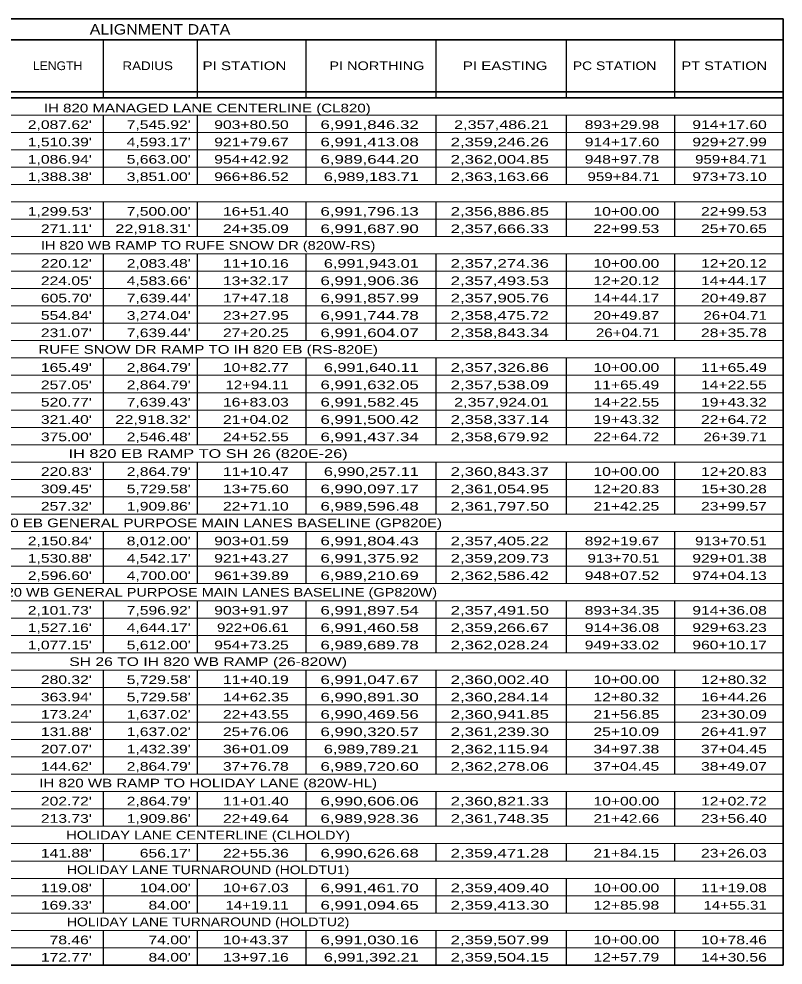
# Model space of a CAD drawing. Extents: x 1953053 to 1967065, y 7363860 to 7371201.
# Drawn here: x 1962633 to 1963690, y 7368856 to 7370165 of the extents above; entities that cross this region are included whole.
import ezdxf
from ezdxf.enums import TextEntityAlignment as Align

# ---------------------------------------------------------------- set-up
doc = ezdxf.new("R2010")
doc.units = 0
doc.header["$LTSCALE"] = 4.8
doc.layers.add('10', color=7, linetype='Continuous')
doc.layers.add('12', color=7, linetype='Continuous', lineweight=25)

msp = doc.modelspace()

# ---------------------------------------------------------------- linework, layer by layer
at = {"layer": '12', "lineweight": 35}
for p, q in [((1963689.794, 7370164.879), (1961966.462, 7370164.879)), ((1963689.794, 7368855.748), (1963689.794, 7370164.879)), ((1961966.462, 7370136.079), (1963689.794, 7370136.079)), ((1961966.462, 7370064.079), (1963689.794, 7370064.079)), ((1961966.462, 7370055.746), (1963689.794, 7370055.746)), ((1961966.462, 7368855.748), (1963689.794, 7368855.748))]:
    msp.add_line(p, q, dxfattribs=at)
at = {"layer": '12'}
for p, q in [((1962749.794, 7370136.079), (1962749.794, 7370055.746)), ((1962879.794, 7370136.079), (1962879.794, 7370055.746)), ((1963029.794, 7370136.079), (1963029.794, 7370055.746)), ((1963209.794, 7370136.079), (1963209.794, 7370055.746)), ((1963389.794, 7370136.079), (1963389.794, 7370055.746)), ((1963539.794, 7370136.079), (1963539.794, 7370055.746)), ((1962749.794, 7370031.746), (1962749.794, 7369935.746)), ((1962879.794, 7370031.746), (1962879.794, 7369935.746)), ((1963029.794, 7370031.746), (1963029.794, 7369935.746)), ((1963209.794, 7370031.746), (1963209.794, 7369935.746)), ((1963389.794, 7370031.746), (1963389.794, 7369935.746)), ((1963539.794, 7370031.746), (1963539.794, 7369935.746)), ((1962749.794, 7369911.746), (1962749.794, 7369863.746)), ((1962879.794, 7369911.746), (1962879.794, 7369863.746)), ((1963029.794, 7369911.746), (1963029.794, 7369863.746)), ((1963209.794, 7369911.746), (1963209.794, 7369863.746)), ((1963389.794, 7369911.746), (1963389.794, 7369863.746)), ((1963539.794, 7369911.746), (1963539.794, 7369863.746)), ((1962749.794, 7369839.746), (1962749.794, 7369719.746)), ((1962879.794, 7369839.746), (1962879.794, 7369719.746)), ((1963029.794, 7369839.746), (1963029.794, 7369719.746)), ((1963209.794, 7369839.746), (1963209.794, 7369719.746)), ((1963389.794, 7369839.746), (1963389.794, 7369719.746)), ((1963539.794, 7369839.746), (1963539.794, 7369719.746)), ((1962749.794, 7369695.746), (1962749.794, 7369575.746)), ((1962879.794, 7369695.746), (1962879.794, 7369575.746)), ((1963029.794, 7369695.746), (1963029.794, 7369575.746)), ((1963209.794, 7369695.746), (1963209.794, 7369575.746)), ((1963389.794, 7369695.746), (1963389.794, 7369575.746)), ((1963539.794, 7369695.746), (1963539.794, 7369575.746)), ((1962749.794, 7369551.746), (1962749.794, 7369479.746)), ((1962879.794, 7369551.746), (1962879.794, 7369479.746)), ((1963029.794, 7369551.746), (1963029.794, 7369479.746)), ((1963209.794, 7369551.746), (1963209.794, 7369479.746)), ((1963389.794, 7369551.746), (1963389.794, 7369479.746)), ((1963539.794, 7369551.746), (1963539.794, 7369479.746)), ((1962749.794, 7369455.746), (1962749.794, 7369383.746)), ((1962879.794, 7369455.746), (1962879.794, 7369383.746)), ((1963029.794, 7369455.746), (1963029.794, 7369383.746)), ((1963209.794, 7369455.746), (1963209.794, 7369383.746)), ((1963389.794, 7369455.746), (1963389.794, 7369383.746)), ((1963539.794, 7369455.746), (1963539.794, 7369383.746)), ((1962749.794, 7369359.746), (1962749.794, 7369287.746)), ((1962879.794, 7369359.746), (1962879.794, 7369287.746)), ((1963029.794, 7369359.746), (1963029.794, 7369287.746)), ((1963209.794, 7369359.746), (1963209.794, 7369287.746)), ((1963389.794, 7369359.746), (1963389.794, 7369287.746)), ((1963539.794, 7369359.746), (1963539.794, 7369287.746)), ((1962749.794, 7369263.746), (1962749.794, 7369119.746)), ((1962879.794, 7369263.746), (1962879.794, 7369119.746)), ((1963029.794, 7369263.746), (1963029.794, 7369119.746)), ((1963209.794, 7369263.746), (1963209.794, 7369119.746)), ((1963389.794, 7369263.746), (1963389.794, 7369119.746)), ((1963539.794, 7369263.746), (1963539.794, 7369119.746)), ((1962749.794, 7369095.746), (1962749.794, 7369047.747)), ((1962879.794, 7369095.746), (1962879.794, 7369047.747)), ((1963029.794, 7369095.746), (1963029.794, 7369047.747)), ((1963209.794, 7369095.746), (1963209.794, 7369047.747)), ((1963389.794, 7369095.746), (1963389.794, 7369047.747)), ((1963539.794, 7369095.746), (1963539.794, 7369047.747)), ((1962749.794, 7369023.747), (1962749.794, 7368999.747)), ((1962879.794, 7369023.747), (1962879.794, 7368999.747)), ((1963029.794, 7369023.747), (1963029.794, 7368999.747)), ((1963209.794, 7369023.747), (1963209.794, 7368999.747)), ((1963389.794, 7369023.747), (1963389.794, 7368999.747)), ((1963539.794, 7369023.747), (1963539.794, 7368999.747)), ((1962749.794, 7368975.747), (1962749.794, 7368927.747)), ((1962879.794, 7368975.747), (1962879.794, 7368927.747)), ((1963029.794, 7368975.747), (1963029.794, 7368927.747)), ((1963209.794, 7368975.747), (1963209.794, 7368927.747)), ((1963389.794, 7368975.747), (1963389.794, 7368927.747)), ((1963539.794, 7368975.747), (1963539.794, 7368927.747)), ((1962749.794, 7368903.747), (1962749.794, 7368855.747)), ((1962879.794, 7368903.747), (1962879.794, 7368855.747)), ((1963029.794, 7368903.747), (1963029.794, 7368855.747)), ((1963209.794, 7368903.747), (1963209.794, 7368855.747)), ((1963389.794, 7368903.747), (1963389.794, 7368855.747)), ((1963539.794, 7368903.747), (1963539.794, 7368855.747))]:
    msp.add_line(p, q, dxfattribs=at)
at = {"layer": '12', "lineweight": 13}
for p, q in [((1961966.462, 7370031.746), (1963689.794, 7370031.746)), ((1961966.462, 7370007.746), (1963689.794, 7370007.746)), ((1961966.462, 7369983.746), (1963689.794, 7369983.746)), ((1961966.462, 7369959.746), (1963689.794, 7369959.746)), ((1961966.462, 7369935.746), (1963689.794, 7369935.746)), ((1961966.462, 7369911.746), (1963689.794, 7369911.746)), ((1961966.462, 7369887.746), (1963689.794, 7369887.746)), ((1961966.462, 7369863.746), (1963689.794, 7369863.746)), ((1961966.462, 7369839.746), (1963689.794, 7369839.746)), ((1961966.462, 7369815.746), (1963689.794, 7369815.746)), ((1961966.462, 7369791.746), (1963689.794, 7369791.746)), ((1961966.462, 7369767.746), (1963689.794, 7369767.746)), ((1961966.462, 7369743.746), (1963689.794, 7369743.746)), ((1961966.462, 7369719.746), (1963689.794, 7369719.746)), ((1961966.462, 7369695.746), (1963689.794, 7369695.746)), ((1961966.462, 7369671.746), (1963689.794, 7369671.746)), ((1961966.462, 7369647.746), (1963689.794, 7369647.746)), ((1961966.462, 7369623.746), (1963689.794, 7369623.746)), ((1961966.462, 7369599.746), (1963689.794, 7369599.746)), ((1961966.462, 7369575.746), (1963689.794, 7369575.746)), ((1961966.462, 7369527.746), (1963689.794, 7369527.746)), ((1961966.462, 7369503.746), (1963689.794, 7369503.746)), ((1961966.462, 7369479.746), (1963689.794, 7369479.746)), ((1961966.462, 7369455.746), (1963689.794, 7369455.746)), ((1961966.462, 7369431.746), (1963689.794, 7369431.746)), ((1961966.462, 7369407.746), (1963689.794, 7369407.746)), ((1961966.462, 7369383.746), (1963689.794, 7369383.746)), ((1961966.462, 7369359.746), (1963689.794, 7369359.746)), ((1961966.462, 7369335.746), (1963689.794, 7369335.746)), ((1961966.462, 7369311.746), (1963689.794, 7369311.746)), ((1961966.462, 7369287.746), (1963689.794, 7369287.746)), ((1961966.462, 7369263.746), (1963689.794, 7369263.746)), ((1961966.462, 7369239.746), (1963689.794, 7369239.746)), ((1961966.462, 7369215.746), (1963689.794, 7369215.746)), ((1961966.462, 7369191.746), (1963689.794, 7369191.746)), ((1961966.462, 7369167.746), (1963689.794, 7369167.746)), ((1961966.462, 7369143.746), (1963689.794, 7369143.746)), ((1961966.462, 7369119.746), (1963689.794, 7369119.746)), ((1961966.462, 7369095.746), (1963689.794, 7369095.746)), ((1961966.462, 7369071.746), (1963689.794, 7369071.746)), ((1961966.462, 7369047.747), (1963689.794, 7369047.747)), ((1961966.462, 7369023.747), (1963689.794, 7369023.747)), ((1961966.462, 7368999.747), (1963689.794, 7368999.747)), ((1961966.462, 7368975.747), (1963689.794, 7368975.747)), ((1961966.462, 7368951.747), (1963689.794, 7368951.747)), ((1961966.462, 7368927.748), (1963689.794, 7368927.748)), ((1961966.462, 7368903.748), (1963689.794, 7368903.748)), ((1961966.462, 7368879.748), (1963689.794, 7368879.748))]:
    msp.add_line(p, q, dxfattribs=at)
msp.add_lwpolyline([(1961966.462, 7369551.746), (1962489.198, 7369551.746), (1963689.794, 7369551.746)], dxfattribs=at)

# ---------------------------------------------------------------- texts
at = {"layer": '10'}
for s, width, p in [('IH 820 MANAGED LANE CENTERLINE (CL820)', 1.3, (1962893.586, 7370035.509)), ('IH 820 WB RAMP TO RUFE SNOW DR (820W-RS)', 1.25, (1962894.794, 7369845.54)), ('RUFE SNOW DR RAMP TO IH 820 EB (RS-820E)', 1.3, (1962894.794, 7369701.54)), ('IH 820 EB RAMP TO SH 26 (820E-26)', 1.4, (1962894.794, 7369557.54)), ('IH 820 EB GENERAL PURPOSE MAIN LANES BASELINE (GP820E)', 1.3, (1962894.795, 7369461.54)), ('IH 820 WB GENERAL PURPOSE MAIN LANES BASELINE (GP820W)', 1.25, (1962894.795, 7369365.54)), ('SH 26 TO IH 820 WB RAMP (26-820W)', 1.35, (1962894.794, 7369269.54)), ('IH 820 WB RAMP TO HOLIDAY LANE (820W-HL)', 1.3, (1962894.794, 7369101.54)), ('HOLIDAY LANE CENTERLINE (CLHOLDY)', 1.25, (1962894.794, 7369029.541)), ('HOLIDAY LANE TURNAROUND (HOLDTU1)', 1.2, (1962894.794, 7368981.541)), ('HOLIDAY LANE TURNAROUND (HOLDTU2)', 1.2, (1962894.794, 7368909.542))]:
    msp.add_text(s, height=12, dxfattribs=dict(at, width=width)).set_placement(p, align=Align.CENTER)
for s, width, p in [("2,087.62'", 1.35, (1962733.918, 7370012.573)), ("7,545.92'", 1.35, (1962870.687, 7370012.573)), ('903+80.50', 1.35, (1963006.231, 7370012.573)), ('6,991,846.32', 1.45, (1963185.996, 7370012.573)), ('2,357,486.21', 1.4, (1963365.996, 7370012.573)), ('893+29.98', 1.35, (1963518.574, 7370012.573)), ('914+17.60', 1.35, (1963667.306, 7370012.573)), ("1,510.39'", 1.35, (1962733.918, 7369988.573)), ("4,593.17'", 1.35, (1962870.687, 7369988.573)), ('921+79.67', 1.35, (1963006.231, 7369988.573)), ('6,991,413.08', 1.45, (1963185.996, 7369988.573)), ('2,359,246.26', 1.45, (1963365.996, 7369988.573)), ('914+17.60', 1.35, (1963518.574, 7369988.573)), ('929+27.99', 1.35, (1963667.306, 7369988.573)), ("1,086.94'", 1.35, (1962733.918, 7369964.573)), ("5,663.00'", 1.35, (1962870.687, 7369964.573)), ('954+42.92', 1.35, (1963006.231, 7369964.573)), ('6,989,644.20', 1.45, (1963185.996, 7369964.573)), ('2,362,004.85', 1.45, (1963365.996, 7369964.573)), ('948+97.78', 1.35, (1963518.574, 7369964.573)), ('959+84.71', 1.3, (1963667.306, 7369964.573)), ("1,388.38'", 1.35, (1962733.918, 7369940.573)), ("3,851.00'", 1.35, (1962870.687, 7369940.573)), ('966+86.52', 1.35, (1963006.231, 7369940.573)), ('6,989,183.71', 1.4, (1963185.996, 7369940.573)), ('2,363,163.66', 1.45, (1963365.996, 7369940.573)), ('959+84.71', 1.3, (1963518.574, 7369940.573)), ('973+73.10', 1.35, (1963667.306, 7369940.573)), ("1,299.53'", 1.35, (1962733.918, 7369892.573)), ("7,500.00'", 1.35, (1962870.687, 7369892.573)), ('16+51.40', 1.35, (1963006.231, 7369892.573)), ('6,991,796.13', 1.45, (1963185.996, 7369892.573)), ('2,356,886.85', 1.45, (1963365.996, 7369892.573)), ('10+00.00', 1.35, (1963518.574, 7369892.573)), ('22+99.53', 1.35, (1963667.306, 7369892.573)), ("271.11'", 1.35, (1962733.918, 7369868.573)), ("22,918.31'", 1.4, (1962870.687, 7369868.573)), ('24+35.09', 1.35, (1963006.231, 7369868.573)), ('6,991,687.90', 1.45, (1963185.996, 7369868.573)), ('2,357,666.33', 1.45, (1963365.996, 7369868.573)), ('22+99.53', 1.35, (1963518.574, 7369868.573)), ('25+70.65', 1.35, (1963667.306, 7369868.573)), ("220.12'", 1.35, (1962733.918, 7369820.573)), ("2,083.48'", 1.35, (1962870.687, 7369820.573)), ('11+10.16', 1.35, (1963006.231, 7369820.573)), ('6,991,943.01', 1.4, (1963185.996, 7369820.573)), ('2,357,274.36', 1.45, (1963365.996, 7369820.573)), ('10+00.00', 1.35, (1963518.574, 7369820.573)), ('12+20.12', 1.35, (1963667.306, 7369820.573)), ("224.05'", 1.35, (1962733.918, 7369796.573)), ("4,583.66'", 1.35, (1962870.687, 7369796.573)), ('13+32.17', 1.35, (1963006.231, 7369796.573)), ('6,991,906.36', 1.45, (1963185.996, 7369796.573)), ('2,357,493.53', 1.45, (1963365.996, 7369796.573)), ('12+20.12', 1.35, (1963518.574, 7369796.573)), ('14+44.17', 1.35, (1963667.306, 7369796.573)), ("605.70'", 1.35, (1962733.918, 7369772.573)), ("7,639.44'", 1.35, (1962870.687, 7369772.573)), ('17+47.18', 1.35, (1963006.231, 7369772.573)), ('6,991,857.99', 1.45, (1963185.996, 7369772.573)), ('2,357,905.76', 1.45, (1963365.996, 7369772.573)), ('14+44.17', 1.35, (1963518.574, 7369772.573)), ('20+49.87', 1.35, (1963667.306, 7369772.573)), ("554.84'", 1.35, (1962733.918, 7369748.573)), ("3,274.04'", 1.35, (1962870.687, 7369748.573)), ('23+27.95', 1.35, (1963006.231, 7369748.573)), ('6,991,744.78', 1.45, (1963185.996, 7369748.573)), ('2,358,475.72', 1.45, (1963365.996, 7369748.573)), ('20+49.87', 1.35, (1963518.574, 7369748.573)), ('26+04.71', 1.3, (1963667.306, 7369748.573)), ("231.07'", 1.35, (1962733.918, 7369724.573)), ("7,639.44'", 1.35, (1962870.687, 7369724.573)), ('27+20.25', 1.35, (1963006.231, 7369724.573)), ('6,991,604.07', 1.45, (1963185.996, 7369724.573)), ('2,358,843.34', 1.45, (1963365.996, 7369724.573)), ('26+04.71', 1.3, (1963518.574, 7369724.573)), ('28+35.78', 1.35, (1963667.306, 7369724.573)), ("165.49'", 1.35, (1962733.918, 7369676.573)), ("2,864.79'", 1.35, (1962870.687, 7369676.573)), ('10+82.77', 1.35, (1963006.231, 7369676.573)), ('6,991,640.11', 1.4, (1963185.996, 7369676.573)), ('2,357,326.86', 1.45, (1963365.996, 7369676.573)), ('10+00.00', 1.35, (1963518.574, 7369676.573)), ('11+65.49', 1.35, (1963667.306, 7369676.573)), ("257.05'", 1.35, (1962733.918, 7369652.573)), ("2,864.79'", 1.35, (1962870.687, 7369652.573)), ('12+94.11', 1.3, (1963006.231, 7369652.573)), ('6,991,632.05', 1.45, (1963185.996, 7369652.573)), ('2,357,538.09', 1.45, (1963365.996, 7369652.573)), ('11+65.49', 1.35, (1963518.574, 7369652.573)), ('14+22.55', 1.35, (1963667.306, 7369652.573)), ("520.77'", 1.35, (1962733.918, 7369628.573)), ("7,639.43'", 1.35, (1962870.687, 7369628.573)), ('16+83.03', 1.35, (1963006.231, 7369628.573)), ('6,991,582.45', 1.45, (1963185.996, 7369628.573)), ('2,357,924.01', 1.4, (1963365.996, 7369628.573)), ('14+22.55', 1.35, (1963518.574, 7369628.573)), ('19+43.32', 1.35, (1963667.306, 7369628.573)), ("321.40'", 1.35, (1962733.918, 7369604.573)), ("22,918.32'", 1.4, (1962870.687, 7369604.573)), ('21+04.02', 1.35, (1963006.231, 7369604.573)), ('6,991,500.42', 1.45, (1963185.996, 7369604.573)), ('2,358,337.14', 1.45, (1963365.996, 7369604.573)), ('19+43.32', 1.35, (1963518.574, 7369604.573)), ('22+64.72', 1.35, (1963667.306, 7369604.573)), ("375.00'", 1.35, (1962733.918, 7369580.573)), ("2,546.48'", 1.35, (1962870.687, 7369580.573)), ('24+52.55', 1.35, (1963006.231, 7369580.573)), ('6,991,437.34', 1.45, (1963185.996, 7369580.573)), ('2,358,679.92', 1.45, (1963365.996, 7369580.573)), ('22+64.72', 1.35, (1963518.574, 7369580.573)), ('26+39.71', 1.3, (1963667.306, 7369580.573)), ("220.83'", 1.35, (1962733.918, 7369532.573)), ("2,864.79'", 1.35, (1962870.687, 7369532.573)), ('11+10.47', 1.35, (1963006.231, 7369532.573)), ('6,990,257.11', 1.4, (1963185.996, 7369532.573)), ('2,360,843.37', 1.45, (1963365.996, 7369532.573)), ('10+00.00', 1.35, (1963518.574, 7369532.573)), ('12+20.83', 1.35, (1963667.306, 7369532.573)), ("309.45'", 1.35, (1962733.918, 7369508.573)), ("5,729.58'", 1.35, (1962870.687, 7369508.573)), ('13+75.60', 1.35, (1963006.231, 7369508.573)), ('6,990,097.17', 1.45, (1963185.996, 7369508.573)), ('2,361,054.95', 1.45, (1963365.996, 7369508.573)), ('12+20.83', 1.35, (1963518.574, 7369508.573)), ('15+30.28', 1.35, (1963667.306, 7369508.573)), ("257.32'", 1.35, (1962733.918, 7369484.573)), ("1,909.86'", 1.35, (1962870.687, 7369484.573)), ('22+71.10', 1.35, (1963006.231, 7369484.573)), ('6,989,596.48', 1.45, (1963185.996, 7369484.573)), ('2,361,797.50', 1.45, (1963365.996, 7369484.573)), ('21+42.25', 1.35, (1963518.574, 7369484.573)), ('23+99.57', 1.35, (1963667.306, 7369484.573)), ("2,150.84'", 1.35, (1962733.918, 7369436.573)), ("8,012.00'", 1.35, (1962870.687, 7369436.573)), ('903+01.59', 1.35, (1963006.231, 7369436.573)), ('6,991,804.43', 1.45, (1963185.996, 7369436.573)), ('2,357,405.22', 1.45, (1963365.996, 7369436.573)), ('892+19.67', 1.35, (1963518.574, 7369436.573)), ('913+70.51', 1.3, (1963667.306, 7369436.573)), ("1,530.88'", 1.35, (1962733.918, 7369412.573)), ("4,542.17'", 1.35, (1962870.687, 7369412.573)), ('921+43.27', 1.35, (1963006.231, 7369412.573)), ('6,991,375.92', 1.45, (1963185.996, 7369412.573)), ('2,359,209.73', 1.45, (1963365.996, 7369412.573)), ('913+70.51', 1.3, (1963518.574, 7369412.573)), ('929+01.38', 1.35, (1963667.306, 7369412.573)), ("2,596.60'", 1.35, (1962733.918, 7369388.573)), ("4,700.00'", 1.35, (1962870.687, 7369388.573)), ('961+39.89', 1.35, (1963006.231, 7369388.573)), ('6,989,210.69', 1.45, (1963185.996, 7369388.573)), ('2,362,586.42', 1.45, (1963365.996, 7369388.573)), ('948+07.52', 1.35, (1963518.574, 7369388.573)), ('974+04.13', 1.35, (1963667.306, 7369388.573)), ("2,101.73'", 1.35, (1962733.918, 7369340.573)), ("7,596.92'", 1.35, (1962870.687, 7369340.573)), ('903+91.97', 1.35, (1963006.231, 7369340.573)), ('6,991,897.54', 1.45, (1963185.996, 7369340.573)), ('2,357,491.50', 1.45, (1963365.996, 7369340.573)), ('893+34.35', 1.35, (1963518.574, 7369340.573)), ('914+36.08', 1.35, (1963667.306, 7369340.573)), ("1,527.16'", 1.35, (1962733.918, 7369316.573)), ("4,644.17'", 1.35, (1962870.687, 7369316.573)), ('922+06.61', 1.3, (1963006.231, 7369316.573)), ('6,991,460.58', 1.45, (1963185.996, 7369316.573)), ('2,359,266.67', 1.45, (1963365.996, 7369316.573)), ('914+36.08', 1.35, (1963518.574, 7369316.573)), ('929+63.23', 1.35, (1963667.306, 7369316.573)), ("1,077.15'", 1.35, (1962733.918, 7369292.573)), ("5,612.00'", 1.35, (1962870.687, 7369292.573)), ('954+73.25', 1.35, (1963006.231, 7369292.573)), ('6,989,689.78', 1.45, (1963185.996, 7369292.573)), ('2,362,028.24', 1.45, (1963365.996, 7369292.573)), ('949+33.02', 1.35, (1963518.574, 7369292.573)), ('960+10.17', 1.35, (1963667.306, 7369292.573)), ("280.32'", 1.35, (1962733.918, 7369244.573)), ("5,729.58'", 1.35, (1962870.687, 7369244.573)), ('11+40.19', 1.35, (1963006.231, 7369244.573)), ('6,991,047.67', 1.45, (1963185.996, 7369244.573)), ('2,360,002.40', 1.45, (1963365.996, 7369244.573)), ('10+00.00', 1.35, (1963518.574, 7369244.573)), ('12+80.32', 1.35, (1963667.306, 7369244.573)), ("363.94'", 1.35, (1962733.918, 7369220.573)), ("5,729.58'", 1.35, (1962870.687, 7369220.573)), ('14+62.35', 1.35, (1963006.231, 7369220.573)), ('6,990,891.30', 1.45, (1963185.996, 7369220.573)), ('2,360,284.14', 1.45, (1963365.996, 7369220.573)), ('12+80.32', 1.35, (1963518.574, 7369220.573)), ('16+44.26', 1.35, (1963667.306, 7369220.573)), ("173.24'", 1.35, (1962733.918, 7369196.573)), ("1,637.02'", 1.35, (1962870.687, 7369196.573)), ('22+43.55', 1.35, (1963006.231, 7369196.573)), ('6,990,469.56', 1.45, (1963185.996, 7369196.573)), ('2,360,941.85', 1.45, (1963365.996, 7369196.573)), ('21+56.85', 1.35, (1963518.574, 7369196.573)), ('23+30.09', 1.35, (1963667.306, 7369196.573)), ("131.88'", 1.35, (1962733.918, 7369172.573)), ("1,637.02'", 1.35, (1962870.687, 7369172.573)), ('25+76.06', 1.35, (1963006.231, 7369172.573)), ('6,990,320.57', 1.45, (1963185.996, 7369172.573)), ('2,361,239.30', 1.45, (1963365.996, 7369172.573)), ('25+10.09', 1.35, (1963518.574, 7369172.573)), ('26+41.97', 1.35, (1963667.306, 7369172.573)), ("207.07'", 1.35, (1962733.918, 7369148.573)), ("1,432.39'", 1.35, (1962870.687, 7369148.573)), ('36+01.09', 1.35, (1963006.231, 7369148.573)), ('6,989,789.21', 1.4, (1963185.996, 7369148.573)), ('2,362,115.94', 1.45, (1963365.996, 7369148.573)), ('34+97.38', 1.35, (1963518.574, 7369148.573)), ('37+04.45', 1.35, (1963667.306, 7369148.573)), ("144.62'", 1.35, (1962733.918, 7369124.573)), ("2,864.79'", 1.35, (1962870.687, 7369124.573)), ('37+76.78', 1.35, (1963006.231, 7369124.573)), ('6,989,720.60', 1.45, (1963185.996, 7369124.573)), ('2,362,278.06', 1.45, (1963365.996, 7369124.573)), ('37+04.45', 1.35, (1963518.574, 7369124.573)), ('38+49.07', 1.35, (1963667.306, 7369124.573)), ("202.72'", 1.35, (1962733.918, 7369076.573)), ("2,864.79'", 1.35, (1962870.687, 7369076.573)), ('11+01.40', 1.35, (1963006.231, 7369076.573)), ('6,990,606.06', 1.45, (1963185.996, 7369076.573)), ('2,360,821.33', 1.45, (1963365.996, 7369076.573)), ('10+00.00', 1.35, (1963518.574, 7369076.573)), ('12+02.72', 1.35, (1963667.306, 7369076.573)), ("213.73'", 1.35, (1962733.918, 7369052.573)), ("1,909.86'", 1.35, (1962870.687, 7369052.573)), ('22+49.64', 1.35, (1963006.231, 7369052.573)), ('6,989,928.36', 1.45, (1963185.996, 7369052.573)), ('2,361,748.35', 1.45, (1963365.996, 7369052.573)), ('21+42.66', 1.35, (1963518.574, 7369052.573)), ('23+56.40', 1.35, (1963667.306, 7369052.573)), ("141.88'", 1.35, (1962733.918, 7369004.574)), ("656.17'", 1.35, (1962870.687, 7369004.574)), ('22+55.36', 1.35, (1963006.231, 7369004.574)), ('6,990,626.68', 1.45, (1963185.996, 7369004.574)), ('2,359,471.28', 1.45, (1963365.996, 7369004.574)), ('21+84.15', 1.35, (1963518.574, 7369004.574)), ('23+26.03', 1.35, (1963667.306, 7369004.574)), ("119.08'", 1.35, (1962733.918, 7368956.574)), ("104.00'", 1.35, (1962870.687, 7368956.574)), ('10+67.03', 1.35, (1963006.231, 7368956.574)), ('6,991,461.70', 1.45, (1963185.996, 7368956.574)), ('2,359,409.40', 1.45, (1963365.996, 7368956.574)), ('10+00.00', 1.35, (1963518.574, 7368956.574)), ('11+19.08', 1.35, (1963667.306, 7368956.574)), ("169.33'", 1.35, (1962733.918, 7368932.574)), ("84.00'", 1.35, (1962870.687, 7368932.574)), ('14+19.11', 1.3, (1963006.231, 7368932.574)), ('6,991,094.65', 1.45, (1963185.996, 7368932.574)), ('2,359,413.30', 1.45, (1963365.996, 7368932.574)), ('12+85.98', 1.35, (1963518.574, 7368932.574)), ('14+55.31', 1.3, (1963667.306, 7368932.574)), ("78.46'", 1.35, (1962733.918, 7368884.575)), ("74.00'", 1.35, (1962870.687, 7368884.575)), ('10+43.37', 1.35, (1963006.231, 7368884.575)), ('6,991,030.16', 1.45, (1963185.996, 7368884.575)), ('2,359,507.99', 1.45, (1963365.996, 7368884.575)), ('10+00.00', 1.35, (1963518.574, 7368884.575)), ('10+78.46', 1.35, (1963667.306, 7368884.575)), ("172.77'", 1.35, (1962733.918, 7368860.575)), ("84.00'", 1.35, (1962870.687, 7368860.575)), ('13+97.16', 1.35, (1963006.231, 7368860.575)), ('6,991,392.21', 1.4, (1963185.996, 7368860.575)), ('2,359,504.15', 1.45, (1963365.996, 7368860.575)), ('12+57.79', 1.35, (1963518.574, 7368860.575)), ('14+30.56', 1.35, (1963667.306, 7368860.575))]:
    msp.add_text(s, height=12, dxfattribs=dict(at, width=width)).set_placement(p, align=Align.RIGHT)
at = {"layer": '12'}
for s, height, width, p in [('ALIGNMENT DATA', 14.4, 1.15, (1962828.235, 7370143.278)), ('LENGTH', 12, 1.05, (1962686.617, 7370094.078)), ('RADIUS', 12, 1.15, (1962811.227, 7370094.078)), ('PI STATION', 12, 1.3, (1962945.031, 7370094.078)), ('PI NORTHING', 12, 1.25, (1963128.106, 7370094.078)), ('PI EASTING', 12, 1.3, (1963305.498, 7370094.078)), ('PC STATION', 12, 1.2, (1963456.803, 7370094.078)), ('PT STATION', 12, 1.25, (1963608.574, 7370094.078))]:
    msp.add_text(s, height=height, dxfattribs=dict(at, width=width)).set_placement(p, align=Align.CENTER)

doc.saveas('drawing.dxf')
